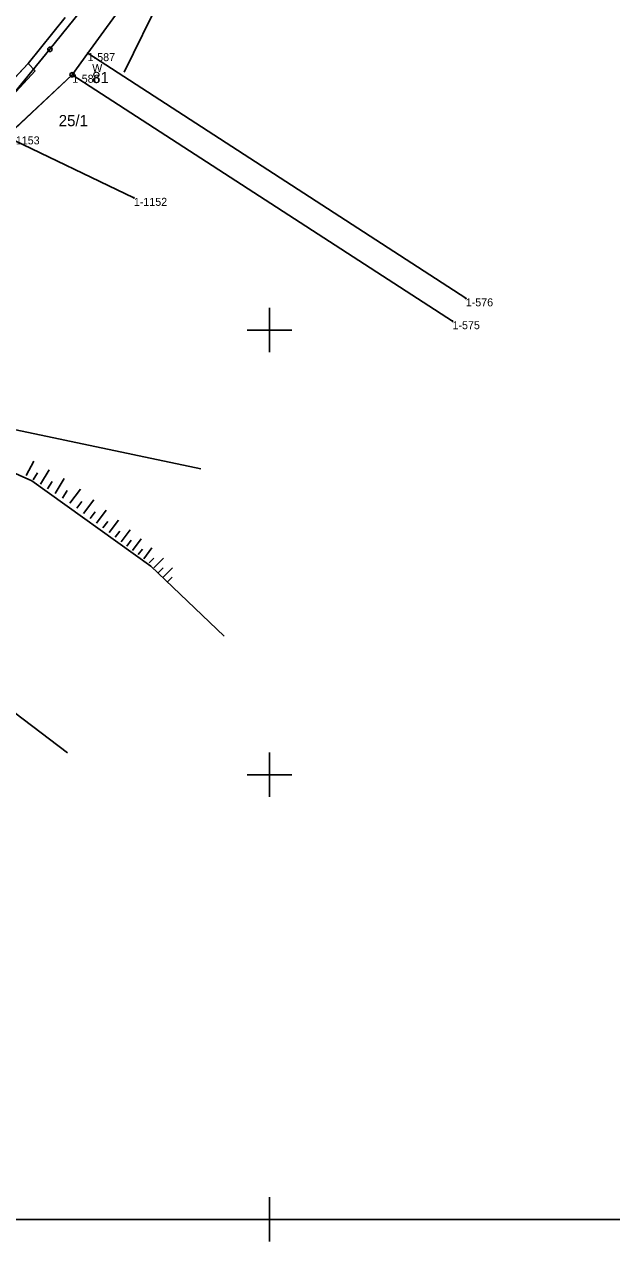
# Model space of a CAD drawing. Extents: x 5598798 to 5599616, y 5661498 to 5662453.
# Drawn here: x 5599122.4 to 5599188.5, y 5661497.5 to 5661634.4 of the extents above; entities that cross this region are included whole.
import ezdxf

# ---------------------------------------------------------------- set-up
doc = ezdxf.new("R2010")
doc.units = 0
for name, color, linetype in [('BUBZ_L_1', 7, 'Continuous'), ('BUIB_L_10', 7, 'Continuous'), ('Dzialki', 7, 'Continuous'), ('Kontury', 7, 'Continuous'), ('KTCR_L_1', 7, 'Continuous'), ('KTJZ_L_0', 7, 'Continuous'), ('KTKR_L_0', 7, 'Continuous'), ('Numery_dzialek', 7, 'Continuous'), ('Numery_punktow', 7, 'Continuous'), ('Numery_uzytkow', 7, 'Continuous'), ('Podzial_sekcyjny_krzyze', 7, 'Continuous'), ('Podzial_sekcyjny_podstawowy', 7, 'Continuous'), ('Punkty', 7, 'Continuous'), ('SUPE_L_3', 7, 'Continuous'), ('SUPW_L_0', 7, 'Continuous'), ('SUSM_T_3', 7, 'Continuous'), ('Uzytki', 7, 'Continuous')]:
    doc.layers.add(name, color=color, linetype=linetype)

# ---------------------------------------------------------------- blocks, each defined once
blk = doc.blocks.new('GRO')
blk.add_circle((0, 0), 0.045)
blk = doc.blocks.new('GRT')
blk.add_circle((0, 0), 0.25)
blk = doc.blocks.new('POINT_DISPLAY')
blk.add_line((0, 0), (0, 0))
blk = doc.blocks.new('4_SUSM04_01')
blk.add_circle((0, 0), 0.25)

msp = doc.modelspace()

# ---------------------------------------------------------------- linework, layer by layer
at = {"layer": 'BUBZ_L_1'}
for p, q in [((5599122.616348, 5661583.638567), (5599123.495293, 5661585.278711)), ((5599123.422372, 5661583.17081), (5599123.915478, 5661583.962165)), ((5599124.22798, 5661582.668823), (5599125.231954, 5661584.280039)), ((5599125.882986, 5661581.637563), (5599126.92345, 5661583.30734)), ((5599125.048098, 5661582.157795), (5599125.559126, 5661582.977913)), ((5599126.732911, 5661581.107962), (5599127.262512, 5661581.957887)), ((5599127.547949, 5661580.546632), (5599128.740206, 5661582.128942)), ((5599128.32259, 5661579.962947), (5599128.906275, 5661580.737588)), ((5599129.081061, 5661579.391446), (5599130.224063, 5661580.908388)), ((5599129.8237, 5661578.831874), (5599130.383271, 5661579.574513)), ((5599130.550837, 5661578.283983), (5599131.646619, 5661579.738257)), ((5599131.262795, 5661577.747528), (5599131.79925, 5661578.459487)), ((5599131.959893, 5661577.222272), (5599133.010406, 5661578.616466)), ((5599132.642439, 5661576.707979), (5599133.156731, 5661577.390525)), ((5599133.310738, 5661576.204422), (5599134.317852, 5661577.54102)), ((5599133.965086, 5661575.711376), (5599134.458132, 5661576.365725)), ((5599134.605776, 5661575.228622), (5599135.571285, 5661576.510002)), ((5599135.233093, 5661574.755945), (5599135.70577, 5661575.383261)), ((5599135.847314, 5661574.293134), (5599136.772935, 5661575.521578)), ((5599136.445966, 5661573.81635), (5599136.99236, 5661574.353999)), ((5599136.978204, 5661573.275456), (5599138.059992, 5661574.339931)), ((5599137.504658, 5661572.740439), (5599138.039675, 5661573.266893)), ((5599138.025392, 5661572.211236), (5599139.083798, 5661573.252703)), ((5599138.540467, 5661571.687783), (5599139.06392, 5661572.202859))]:
    msp.add_line(p, q, dxfattribs=at)
at = {"layer": 'BUIB_L_10'}
msp.add_line((5599149.83, 5661661.97), (5599133.66, 5661629), dxfattribs=at)
at = {"layer": 'Dzialki'}
for p, q in [((5599136.04, 5661640.04), (5599129.55, 5661631.14)), ((5599129.55, 5661631.14), (5599127.81, 5661628.71)), ((5599129.55, 5661631.14), (5599172.06, 5661603.57)), ((5599127.81, 5661628.71), (5599120.4, 5661621.78)), ((5599170.57, 5661601), (5599127.81, 5661628.71)), ((5599120.4, 5661621.78), (5599134.74, 5661614.87))]:
    msp.add_line(p, q, dxfattribs=at)
at = {"layer": 'Kontury'}
for p, q in [((5599129.55, 5661631.14), (5599136.04, 5661640.04)), ((5599127.81, 5661628.71), (5599129.55, 5661631.14)), ((5599113.12, 5661614.97), (5599127.81, 5661628.71)), ((5599127.28, 5661552.45), (5599087.14, 5661583.01))]:
    msp.add_line(p, q, dxfattribs=at)
at = {"layer": 'KTCR_L_1'}
for p, q in [((5599122.86, 5661629.96), (5599114.98, 5661621.62)), ((5599123.66, 5661629.14), (5599122.86, 5661629.96)), ((5599115.95, 5661620.81), (5599123.66, 5661629.14))]:
    msp.add_line(p, q, dxfattribs=at)
at = {"layer": 'KTJZ_L_0'}
for p, q in [((5599122.86, 5661629.96), (5599127.02, 5661635.13)), ((5599114.98, 5661621.62), (5599122.86, 5661629.96))]:
    msp.add_line(p, q, dxfattribs=at)
at = {"layer": 'KTKR_L_0'}
msp.add_line((5599122.86, 5661629.96), (5599114.98, 5661621.62), dxfattribs=at)
at = {"layer": 'Podzial_sekcyjny_krzyze'}
for p, q in [((5599150, 5661597.5), (5599150, 5661602.5)), ((5599147.5, 5661600), (5599152.5, 5661600)), ((5599150, 5661547.5), (5599150, 5661552.5)), ((5599147.5, 5661550), (5599152.5, 5661550)), ((5599150, 5661497.5), (5599150, 5661502.5)), ((5599147.5, 5661500), (5599152.5, 5661500))]:
    msp.add_line(p, q, dxfattribs=at)
at = {"layer": 'Podzial_sekcyjny_podstawowy'}
msp.add_line((5598800, 5661500), (5599200, 5661500), dxfattribs=at)
at = {"layer": 'SUPE_L_3'}
for p, q in [((5599125.304463, 5661631.572851), (5599150.160871, 5661662.612128)), ((5599094.830509, 5661594.368063), (5599125.304463, 5661631.572851)), ((5599142.263788, 5661584.415924), (5599094.830509, 5661594.368063))]:
    msp.add_line(p, q, dxfattribs=at)
at = {"layer": 'SUPW_L_0'}
for p, q in [((5599106.165307, 5661590.648806), (5599123.265858, 5661583.053706)), ((5599106.165307, 5661590.648806), (5599123.265858, 5661583.053706)), ((5599123.265858, 5661583.053706), (5599136.650007, 5661573.463241)), ((5599136.650007, 5661573.463241), (5599144.913264, 5661565.567241))]:
    msp.add_line(p, q, dxfattribs=at)
at = {"layer": 'Uzytki'}
for p, q in [((5599136.04, 5661640.04), (5599129.55, 5661631.14)), ((5599129.55, 5661631.14), (5599127.81, 5661628.71)), ((5599172.06, 5661603.57), (5599129.55, 5661631.14)), ((5599127.81, 5661628.71), (5599113.12, 5661614.97)), ((5599127.81, 5661628.71), (5599170.57, 5661601)), ((5599127.28, 5661552.45), (5599087.14, 5661583.01))]:
    msp.add_line(p, q, dxfattribs=at)

# ---------------------------------------------------------------- block references
at = {"layer": 'BUBZ_L_1'}
msp.add_blockref('POINT_DISPLAY', (5599139.050818, 5661571.169132), dxfattribs=at)
at = {"layer": 'Punkty'}
for name, p in [('GRO', (5599129.55, 5661631.14)), ('GRT', (5599127.81, 5661628.71)), ('GRO', (5599134.74, 5661614.87)), ('GRO', (5599172.06, 5661603.57)), ('GRO', (5599170.57, 5661601))]:
    msp.add_blockref(name, p, dxfattribs=at)
at = {"layer": 'SUSM_T_3'}
msp.add_blockref('4_SUSM04_01', (5599125.304463, 5661631.572851), dxfattribs=at)

# ---------------------------------------------------------------- texts
at = {"layer": 'Numery_dzialek'}
for s, p in [('81', (5599130.060177, 5661627.770243)), ('25/1', (5599126.297151, 5661622.924039))]:
    msp.add_text(s, height=1.26, dxfattribs=at).set_placement(p)
at = {"layer": 'Numery_punktow'}
for s, p in [('1-587', (5599129.55, 5661630.24)), ('1-586', (5599127.81, 5661627.81)), ('1-1153', (5599120.4, 5661620.88)), ('1-1152', (5599134.74, 5661613.97)), ('1-576', (5599172.06, 5661602.67)), ('1-575', (5599170.57, 5661600.1))]:
    msp.add_text(s, height=0.9, dxfattribs=at).set_placement(p)
at = {"layer": 'Numery_uzytkow'}
msp.add_text('W', height=0.9, dxfattribs=at).set_placement((5599130.060177, 5661629.030243))

doc.saveas('drawing.dxf')
